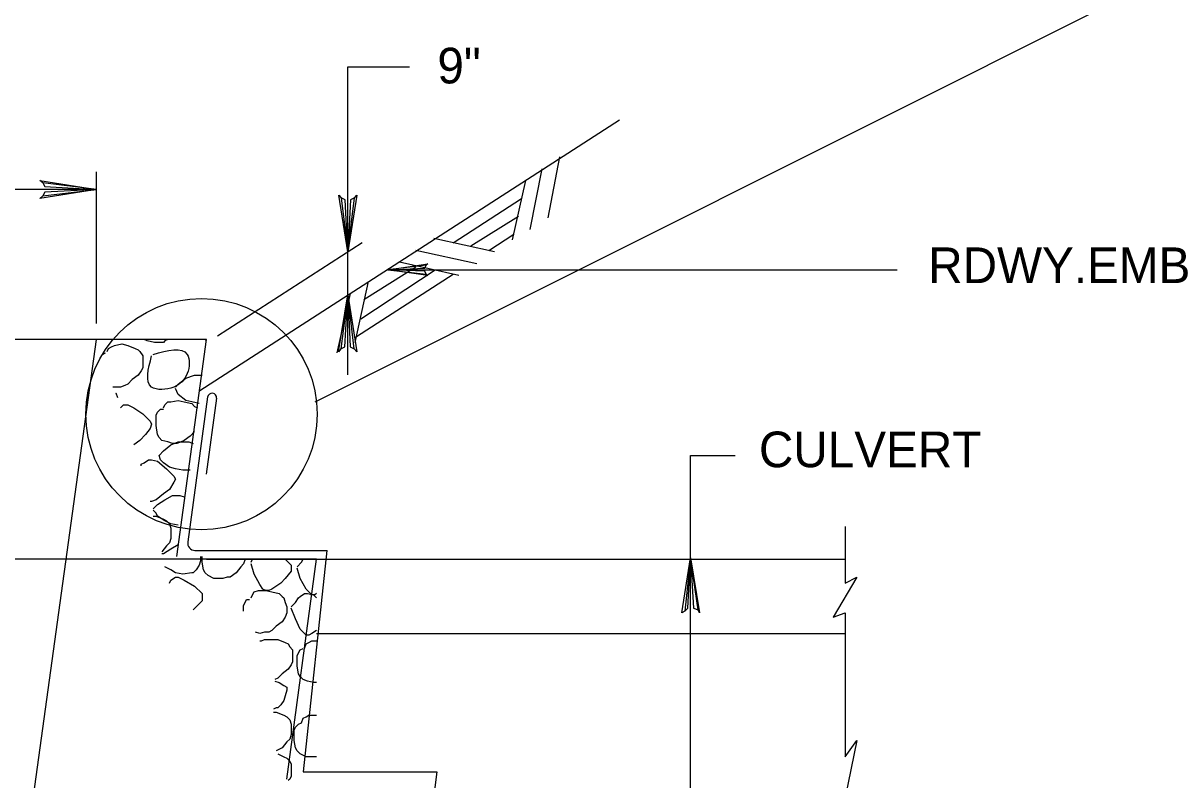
# Model space of a CAD drawing. Extents: x 593 to 1473, y 721 to 1315.
# Drawn here: x 928.2 to 1025.6, y 1182.1 to 1245.8 of the extents above; entities that cross this region are included whole.
import ezdxf

# ---------------------------------------------------------------- set-up
doc = ezdxf.new("R2010")
doc.units = 0
doc.layers.add('1', color=7, linetype='Continuous')
doc.layers.add('2', color=7, linetype='Continuous')

msp = doc.modelspace()

# ---------------------------------------------------------------- linework, layer by layer
at = {"layer": '1'}
for points in [[(929.868, 1232.341), (930.037, 1232.012), (934.408, 1231.771), (929.868, 1232.341), (929.635, 1232.54), (934.408, 1231.771), (930.04, 1231.555), (929.881, 1231.23), (934.408, 1231.771), (929.635, 1231.013), (929.881, 1231.23)], [(956.115, 1231.071), (955.787, 1230.901), (955.545, 1226.53), (956.115, 1231.071), (956.315, 1231.303), (955.545, 1226.53), (955.329, 1230.898), (955.004, 1231.058), (955.545, 1226.53), (954.787, 1231.303), (955.004, 1231.058)], [(954.975, 1218.351), (955.304, 1218.52), (955.545, 1222.892), (954.975, 1218.351), (954.776, 1218.118), (955.545, 1222.892), (955.761, 1218.524), (956.087, 1218.364), (955.545, 1222.892), (956.304, 1218.118), (956.087, 1218.364)]]:
    msp.add_lwpolyline(points, dxfattribs=at)
at = {"layer": '2'}
for p, q in [((952.816, 1213.91), (1039.763, 1257.447)), ((955.545, 1226.53), (955.545, 1242.089)), ((955.545, 1242.089), (960.736, 1242.089)), ((972.408, 1229.396), (973.408, 1234.521)), ((934.408, 1220.489), (934.408, 1233.271)), ((970.908, 1228.396), (971.908, 1233.521)), ((934.408, 1231.771), (915.783, 1231.771)), ((969.408, 1227.521), (970.533, 1232.521)), ((944.591, 1219.466), (956.747, 1227.304)), ((967.908, 1226.521), (962.783, 1227.646)), ((955.545, 1222.892), (955.545, 1226.53)), ((966.408, 1225.521), (961.283, 1226.646)), ((958.908, 1225.021), (1001.783, 1225.021)), ((964.908, 1224.521), (959.908, 1225.646)), ((956.158, 1218.896), (957.283, 1224.021)), ((954.658, 1218.021), (955.783, 1223.021)), ((955.545, 1216.159), (955.545, 1222.892)), ((943.658, 1219.146), (901.783, 1219.146)), ((924.158, 1145.021), (934.408, 1219.146)), ((941.158, 1200.896), (943.658, 1219.146)), ((984.408, 1163.521), (984.408, 1209.396)), ((984.408, 1209.396), (988.158, 1209.396)), ((997.408, 1203.396), (997.408, 1198.646)), ((952.908, 1200.646), (913.408, 1200.646)), ((943.658, 1200.646), (952.908, 1200.646)), ((950.408, 1182.146), (952.908, 1200.646)), ((953.783, 1201.396), (951.783, 1182.771)), ((952.908, 1200.646), (997.408, 1200.646)), ((985.033, 1200.646), (985.408, 1200.646)), ((997.408, 1196.146), (997.408, 1184.021)), ((952.908, 1194.396), (997.408, 1194.396)), ((951.783, 1182.771), (963.033, 1182.771)), ((963.033, 1182.771), (960.783, 1164.271))]:
    msp.add_line(p, q, dxfattribs=at)
for points in [[(943.101, 1214.843), (978.408, 1237.646)], [(964.408, 1227.271), (970.158, 1231.021)], [(965.908, 1227.021), (969.908, 1229.521)], [(967.408, 1226.646), (969.533, 1228.021)], [(956.658, 1220.896), (962.908, 1225.021)], [(956.908, 1222.521), (961.283, 1225.271)], [(962.158, 1224.646), (962.033, 1224.896), (958.908, 1225.021), (962.158, 1224.646), (962.283, 1224.521), (958.908, 1225.021), (962.033, 1225.146), (962.158, 1225.396), (958.908, 1225.021), (962.283, 1225.521), (962.158, 1225.396)], [(956.283, 1219.396), (964.408, 1224.646)], [(938.658, 1219.021), (938.408, 1219.146)], [(940.408, 1219.146), (940.158, 1219.021)], [(943.658, 1219.021), (943.533, 1219.146)], [(935.283, 1218.146), (935.408, 1218.396)], [(935.408, 1218.396), (935.658, 1218.521)], [(935.658, 1218.521), (935.908, 1218.646)], [(935.908, 1218.646), (936.533, 1218.771)], [(936.533, 1218.771), (937.033, 1218.646)], [(937.033, 1218.646), (937.658, 1218.396)], [(937.658, 1218.396), (937.908, 1218.271)], [(937.908, 1218.271), (938.033, 1218.146)], [(938.033, 1218.146), (938.283, 1217.771)], [(939.283, 1218.896), (938.658, 1219.021)], [(940.033, 1218.896), (939.283, 1218.896)], [(940.158, 1219.021), (940.033, 1218.896)], [(934.908, 1217.896), (935.158, 1218.021)], [(934.908, 1217.896), (934.908, 1217.896)], [(938.283, 1217.771), (938.283, 1217.396)], [(938.283, 1217.396), (938.283, 1217.146)], [(938.283, 1217.146), (938.283, 1216.771)], [(937.908, 1216.146), (937.408, 1215.771)], [(938.158, 1216.521), (937.908, 1216.146)], [(938.283, 1216.771), (938.158, 1216.521)], [(941.908, 1215.896), (942.658, 1216.146)], [(942.658, 1216.146), (942.783, 1216.146)], [(942.783, 1216.146), (943.283, 1216.146)], [(936.783, 1215.271), (936.408, 1215.146)], [(937.033, 1215.396), (936.783, 1215.271)], [(937.408, 1215.771), (937.033, 1215.396)], [(941.033, 1215.146), (941.283, 1215.396)], [(941.283, 1215.396), (941.908, 1215.896)], [(936.033, 1215.146), (935.783, 1215.146)], [(936.408, 1215.146), (936.033, 1215.146)], [(936.033, 1214.646), (936.033, 1214.646)], [(936.033, 1214.646), (936.158, 1214.271)], [(936.158, 1214.271), (936.158, 1214.271)], [(941.158, 1214.771), (941.033, 1215.021)], [(941.283, 1214.521), (941.158, 1214.771)], [(941.908, 1214.021), (941.283, 1214.521)], [(943.752, 1214.307), (942.081, 1202.105)], [(944.494, 1214.197), (943.62, 1207.815)], [(936.408, 1213.396), (936.658, 1213.646)], [(936.658, 1213.646), (936.908, 1213.646)], [(936.908, 1213.646), (937.033, 1213.646)], [(937.033, 1213.646), (937.533, 1213.396)], [(937.533, 1213.396), (938.283, 1212.896)], [(939.533, 1213.021), (939.783, 1213.271)], [(939.783, 1213.271), (940.033, 1213.271)], [(940.033, 1213.396), (940.158, 1213.646)], [(940.158, 1213.646), (940.408, 1213.896)], [(940.408, 1213.896), (940.658, 1213.896)], [(940.658, 1213.896), (941.283, 1214.021)], [(941.283, 1214.021), (941.783, 1213.896)], [(941.783, 1213.896), (942.408, 1213.771)], [(942.408, 1213.896), (941.908, 1214.021)], [(943.033, 1213.771), (942.408, 1213.896)], [(942.408, 1213.771), (942.658, 1213.521)], [(942.658, 1213.521), (942.908, 1213.396)], [(938.283, 1212.896), (938.908, 1212.271)], [(938.908, 1212.271), (939.033, 1212.021)], [(939.408, 1212.771), (939.533, 1213.021)], [(939.408, 1212.396), (939.408, 1212.771)], [(939.408, 1211.896), (939.408, 1212.396)], [(938.908, 1211.646), (938.533, 1211.146)], [(939.033, 1212.021), (938.908, 1211.646)], [(939.533, 1211.146), (939.408, 1211.896)], [(942.658, 1211.396), (942.283, 1211.021)], [(938.033, 1210.646), (937.533, 1210.271)], [(938.533, 1211.146), (938.033, 1210.646)], [(939.658, 1210.896), (939.533, 1211.146)], [(939.908, 1210.646), (939.658, 1210.896)], [(940.408, 1210.521), (939.908, 1210.646)], [(940.783, 1210.396), (940.408, 1210.521)], [(940.658, 1210.271), (941.283, 1210.521)], [(941.158, 1210.396), (940.783, 1210.396)], [(941.533, 1210.521), (941.158, 1210.396)], [(941.283, 1210.521), (941.408, 1210.521)], [(941.408, 1210.521), (941.908, 1210.521)], [(941.783, 1210.646), (941.533, 1210.521)], [(942.283, 1211.021), (941.783, 1210.646)], [(941.908, 1210.521), (942.158, 1210.521)], [(942.158, 1210.521), (942.533, 1210.396)], [(939.658, 1209.396), (940.033, 1209.771)], [(939.783, 1209.021), (939.658, 1209.396)], [(940.033, 1209.771), (940.658, 1210.271)], [(938.158, 1208.646), (938.408, 1208.771)], [(938.158, 1208.521), (938.158, 1208.646)], [(938.408, 1208.771), (938.783, 1209.021)], [(938.783, 1209.021), (938.908, 1209.021)], [(938.908, 1209.021), (939.033, 1209.021)], [(939.033, 1209.021), (939.533, 1208.896)], [(939.533, 1208.896), (940.283, 1208.271)], [(940.033, 1208.771), (939.783, 1209.021)], [(940.533, 1208.396), (940.033, 1208.771)], [(941.033, 1208.271), (940.533, 1208.396)], [(940.283, 1208.271), (940.908, 1207.646)], [(940.908, 1207.646), (941.033, 1207.396)], [(941.033, 1207.396), (940.908, 1207.146)], [(941.658, 1208.146), (941.033, 1208.271)], [(942.283, 1208.146), (941.658, 1208.146)], [(940.533, 1206.521), (940.033, 1206.146)], [(940.908, 1207.146), (940.533, 1206.521)], [(939.033, 1205.521), (938.908, 1205.521)], [(939.408, 1205.646), (939.033, 1205.521)], [(940.033, 1206.146), (939.408, 1205.646)], [(939.533, 1205.271), (940.158, 1205.646)], [(940.158, 1205.646), (940.783, 1206.021)], [(940.783, 1206.021), (941.033, 1206.021)], [(941.033, 1206.021), (941.408, 1206.021)], [(941.408, 1206.021), (941.783, 1205.896)], [(939.158, 1204.896), (939.533, 1205.271)], [(939.408, 1204.521), (939.158, 1204.771)], [(939.533, 1204.271), (939.408, 1204.521)], [(939.158, 1204.271), (939.408, 1204.271)], [(939.408, 1204.271), (940.033, 1204.021)], [(940.158, 1203.896), (939.533, 1204.271)], [(940.033, 1204.021), (940.283, 1203.896)], [(940.658, 1203.646), (940.158, 1203.896)], [(940.283, 1203.896), (940.533, 1203.646)], [(940.533, 1203.646), (940.658, 1203.271)], [(941.283, 1203.521), (940.658, 1203.646)], [(940.658, 1203.271), (940.658, 1203.021)], [(940.658, 1203.021), (940.658, 1202.771)], [(940.658, 1202.771), (940.658, 1202.396)], [(940.283, 1201.771), (939.908, 1201.271)], [(940.533, 1202.021), (940.283, 1201.771)], [(940.658, 1202.396), (940.533, 1202.021)], [(940.658, 1201.521), (941.283, 1201.896)], [(939.908, 1201.146), (940.033, 1201.146)], [(940.033, 1201.146), (940.658, 1201.521)], [(942.695, 1201.396), (953.814, 1201.396)], [(943.158, 1200.896), (943.158, 1200.521)], [(943.283, 1200.396), (943.283, 1200.896)], [(946.908, 1200.646), (946.783, 1200.271)], [(947.408, 1200.396), (947.533, 1200.646)], [(950.283, 1200.646), (950.783, 1200.146)], [(951.658, 1200.396), (951.783, 1200.646)], [(983.908, 1196.271), (984.158, 1196.521), (984.408, 1200.771), (983.908, 1196.271), (983.658, 1196.146), (984.408, 1200.771), (984.658, 1196.521), (985.033, 1196.396), (984.408, 1200.771), (985.158, 1196.146), (985.033, 1196.396)], [(940.658, 1199.771), (940.158, 1200.021)], [(941.033, 1199.521), (940.658, 1199.771)], [(942.783, 1199.771), (942.533, 1199.521)], [(943.033, 1200.146), (942.783, 1199.771)], [(943.158, 1200.521), (943.033, 1200.146)], [(943.408, 1199.771), (943.283, 1200.396)], [(943.533, 1199.521), (943.408, 1199.771)], [(946.533, 1200.021), (946.158, 1199.521)], [(946.783, 1200.271), (946.533, 1200.021)], [(947.658, 1199.396), (947.408, 1200.271)], [(950.783, 1199.646), (950.283, 1199.021)], [(950.783, 1200.146), (950.783, 1199.896)], [(950.783, 1199.896), (950.783, 1199.646)], [(951.283, 1200.021), (951.658, 1200.396)], [(951.533, 1199.021), (951.283, 1199.896)], [(940.533, 1198.646), (940.658, 1198.896)], [(940.533, 1198.646), (940.533, 1198.646)], [(940.658, 1198.896), (941.033, 1199.146)], [(941.658, 1199.396), (941.033, 1199.521)], [(941.033, 1199.146), (941.158, 1199.146)], [(941.158, 1199.146), (941.283, 1199.146)], [(941.283, 1199.146), (941.783, 1198.896)], [(942.408, 1199.521), (941.658, 1199.396)], [(941.783, 1198.896), (942.658, 1198.396)], [(942.533, 1199.521), (942.408, 1199.521)], [(943.783, 1199.271), (943.533, 1199.521)], [(944.283, 1199.021), (943.783, 1199.271)], [(944.658, 1199.021), (944.283, 1199.021)], [(945.033, 1199.021), (944.658, 1199.021)], [(945.408, 1199.146), (945.033, 1199.021)], [(945.658, 1199.146), (945.408, 1199.146)], [(946.158, 1199.521), (945.658, 1199.146)], [(948.158, 1198.521), (947.658, 1199.396)], [(949.908, 1198.646), (949.158, 1198.146)], [(950.283, 1199.021), (949.908, 1198.646)], [(952.033, 1198.146), (951.533, 1199.021)], [(997.408, 1198.646), (998.408, 1199.146), (996.408, 1195.771), (997.408, 1196.146)], [(942.658, 1198.396), (943.283, 1197.771)], [(943.283, 1197.771), (943.283, 1197.521)], [(947.408, 1197.396), (947.533, 1197.646)], [(947.533, 1197.646), (947.658, 1197.896)], [(947.658, 1197.896), (948.033, 1198.021)], [(948.033, 1198.021), (948.658, 1198.021)], [(948.408, 1198.146), (948.158, 1198.521)], [(948.658, 1198.021), (948.408, 1198.146)], [(948.658, 1198.021), (949.158, 1197.896)], [(948.908, 1198.021), (948.658, 1198.021)], [(949.158, 1198.146), (948.908, 1198.021)], [(949.158, 1197.896), (949.783, 1197.771)], [(949.783, 1197.771), (950.033, 1197.521)], [(951.533, 1197.521), (951.908, 1197.771)], [(951.908, 1197.771), (952.033, 1197.771)], [(952.408, 1197.771), (952.033, 1198.146)], [(952.033, 1197.771), (952.158, 1197.771)], [(952.158, 1197.771), (952.658, 1197.646)], [(952.533, 1197.646), (952.408, 1197.771)], [(952.783, 1197.646), (952.533, 1197.646)], [(952.658, 1197.646), (952.908, 1197.396)], [(952.908, 1197.771), (952.783, 1197.646)], [(943.283, 1197.146), (942.783, 1196.646)], [(943.283, 1197.521), (943.283, 1197.146)], [(946.783, 1196.771), (946.908, 1197.021)], [(946.783, 1196.396), (946.783, 1196.771)], [(946.908, 1197.021), (947.033, 1197.271)], [(947.033, 1197.271), (947.283, 1197.271)], [(950.033, 1197.521), (950.158, 1197.396)], [(950.158, 1197.396), (950.283, 1197.021)], [(950.283, 1197.021), (950.408, 1196.646)], [(950.783, 1196.646), (951.158, 1197.021)], [(951.158, 1197.021), (951.408, 1197.396)], [(951.408, 1197.396), (951.533, 1197.521)], [(942.783, 1196.646), (942.533, 1196.396)], [(946.783, 1196.271), (946.783, 1196.396)], [(950.283, 1195.771), (950.033, 1195.396)], [(950.408, 1196.146), (950.283, 1195.771)], [(950.408, 1196.646), (950.408, 1196.396)], [(950.408, 1196.396), (950.408, 1196.146)], [(951.158, 1195.646), (950.783, 1196.521)], [(949.533, 1195.021), (949.158, 1194.646)], [(950.033, 1195.396), (949.533, 1195.021)], [(951.533, 1194.771), (951.158, 1195.646)], [(951.908, 1194.396), (951.533, 1194.771)], [(948.158, 1194.396), (947.783, 1194.521)], [(948.533, 1194.521), (948.158, 1194.396)], [(948.158, 1193.771), (948.283, 1193.771)], [(948.283, 1193.771), (948.533, 1193.896)], [(948.908, 1194.521), (948.533, 1194.521)], [(948.533, 1193.896), (949.158, 1193.896)], [(949.158, 1194.646), (948.908, 1194.521)], [(949.158, 1193.896), (949.658, 1193.896)], [(949.658, 1193.896), (950.283, 1193.646)], [(952.033, 1194.271), (951.908, 1194.396)], [(952.283, 1194.271), (952.033, 1194.271)], [(952.533, 1194.396), (952.283, 1194.271)], [(952.283, 1193.646), (952.533, 1193.771)], [(952.908, 1194.646), (952.533, 1194.396)], [(952.533, 1193.771), (952.908, 1193.771)], [(950.283, 1193.646), (950.533, 1193.521)], [(950.533, 1193.521), (950.658, 1193.271)], [(950.658, 1193.271), (950.908, 1193.021)], [(950.908, 1193.021), (950.908, 1192.646)], [(951.283, 1192.521), (951.408, 1192.771)], [(951.408, 1192.771), (951.533, 1193.021)], [(951.533, 1193.021), (951.783, 1193.146)], [(951.908, 1193.146), (952.033, 1193.521)], [(952.033, 1193.521), (952.283, 1193.646)], [(950.908, 1192.021), (950.783, 1191.771)], [(950.908, 1192.646), (950.908, 1192.396)], [(950.908, 1192.396), (950.908, 1192.021)], [(951.283, 1192.271), (951.283, 1192.521)], [(951.283, 1191.646), (951.283, 1192.271)], [(950.033, 1191.021), (949.658, 1190.646)], [(950.533, 1191.396), (950.033, 1191.021)], [(950.783, 1191.771), (950.533, 1191.396)], [(951.408, 1191.021), (951.283, 1191.646)], [(951.533, 1190.771), (951.408, 1191.021)], [(949.658, 1190.646), (949.408, 1190.521)], [(949.408, 1190.396), (949.783, 1190.271)], [(949.783, 1190.271), (950.158, 1190.021)], [(950.158, 1190.021), (950.408, 1189.896)], [(950.408, 1189.896), (950.408, 1189.646)], [(951.783, 1190.521), (951.533, 1190.771)], [(952.158, 1190.396), (951.783, 1190.521)], [(952.658, 1190.271), (952.158, 1190.396)], [(952.908, 1190.271), (952.658, 1190.271)], [(950.283, 1189.146), (950.158, 1188.771)], [(950.408, 1189.646), (950.283, 1189.146)], [(949.533, 1188.146), (949.283, 1188.021)], [(949.658, 1188.146), (949.533, 1188.146)], [(949.908, 1188.396), (949.658, 1188.146)], [(950.158, 1188.771), (949.908, 1188.396)], [(949.283, 1187.771), (949.533, 1187.771)], [(949.533, 1187.771), (950.158, 1187.521)], [(950.158, 1187.521), (950.408, 1187.396)], [(950.408, 1187.396), (950.658, 1187.146)], [(950.658, 1187.146), (950.783, 1186.771)], [(951.658, 1186.896), (951.783, 1187.271)], [(951.783, 1187.271), (952.033, 1187.396)], [(952.033, 1187.396), (952.283, 1187.521)], [(952.283, 1187.521), (952.908, 1187.521)], [(952.908, 1187.521), (952.908, 1187.521)], [(950.783, 1186.771), (950.783, 1186.521)], [(950.783, 1186.521), (950.783, 1186.271)], [(950.783, 1186.271), (950.783, 1185.896)], [(951.033, 1186.271), (951.158, 1186.521)], [(951.033, 1185.896), (951.033, 1186.271)], [(951.158, 1186.521), (951.408, 1186.771)], [(951.408, 1186.771), (951.658, 1186.896)], [(950.408, 1185.271), (950.033, 1184.771)], [(950.658, 1185.521), (950.408, 1185.271)], [(950.783, 1185.896), (950.658, 1185.521)], [(951.033, 1185.396), (951.033, 1185.896)], [(951.158, 1184.771), (951.033, 1185.396)], [(997.408, 1184.021), (998.408, 1185.396), (996.658, 1176.896), (997.408, 1178.021)], [(950.033, 1184.771), (949.533, 1184.521)], [(949.658, 1184.271), (950.158, 1184.021)], [(950.158, 1184.021), (950.408, 1183.896)], [(951.283, 1184.521), (951.158, 1184.771)], [(951.533, 1184.271), (951.283, 1184.521)], [(952.033, 1184.021), (951.533, 1184.271)], [(952.408, 1184.021), (952.033, 1184.021)], [(952.783, 1184.021), (952.408, 1184.021)], [(952.908, 1184.021), (952.783, 1184.021)], [(950.408, 1183.896), (950.658, 1183.646)], [(950.658, 1183.646), (950.783, 1183.396)], [(950.783, 1183.396), (950.783, 1183.021)], [(950.658, 1182.146), (950.533, 1182.021)], [(950.783, 1182.396), (950.658, 1182.146)], [(950.783, 1183.021), (950.783, 1182.771)], [(950.783, 1182.771), (950.783, 1182.396)]]:
    msp.add_lwpolyline(points, dxfattribs=at)
msp.add_circle((943.235, 1212.866), 9.739, dxfattribs=at)
for centre, radius, start, end in [((944.123, 1214.252), 0.375, 351.60191, 171.60191), ((942.679, 1201.999), 0.605, 170.76772, 270.23126)]:
    msp.add_arc(centre, radius, start, end, dxfattribs=at)
msp.add_spline([(939.158, 1217.896), (942.033, 1217.896), (942.033, 1216.271), (940.908, 1215.146), (939.033, 1215.146), (939.033, 1217.771)], degree=3, dxfattribs=at)

# ---------------------------------------------------------------- texts
for s, p in [('9"', (963.089, 1240.7)), ('RDWY.EMBANKMENT', (1004.408, 1223.896)), ('CULVERT', (990.158, 1208.396))]:
    msp.add_text(s, height=3, dxfattribs=at).set_placement(p)

doc.saveas('drawing.dxf')
